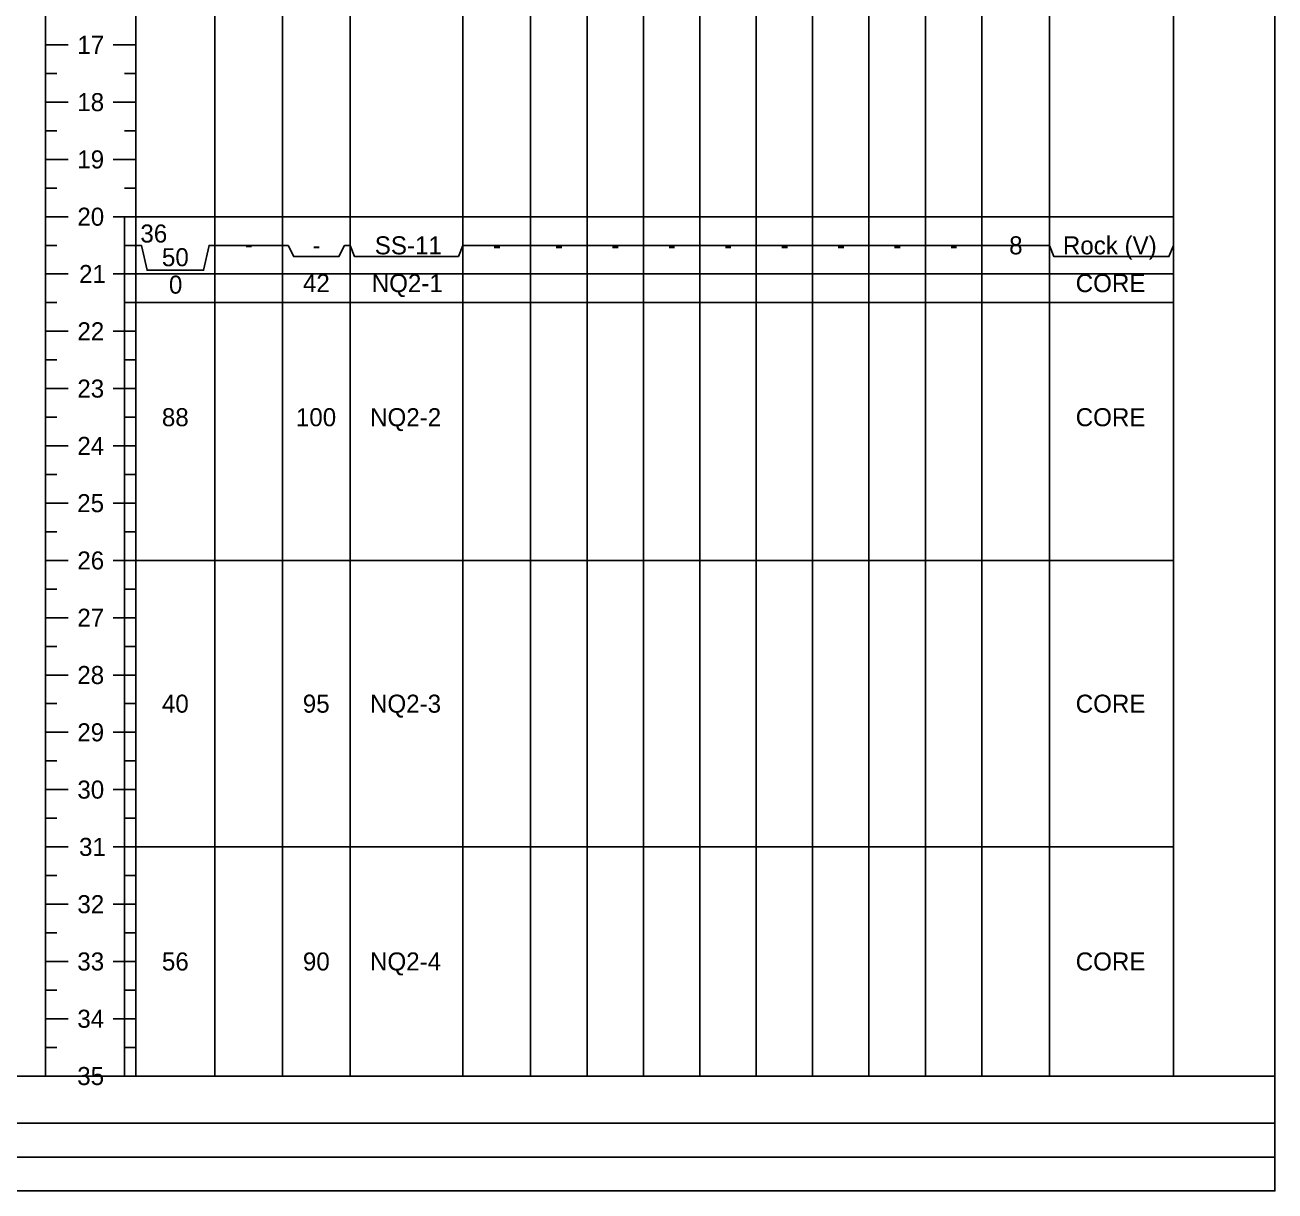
# Model space of a CAD drawing. Extents: x 0 to 0.833, y -0.254 to 0.608.
# Drawn here: x 0.3715 to 0.8333, y -0.2541 to 0.1767 of the extents above; entities that cross this region are included whole.
import ezdxf

# ---------------------------------------------------------------- set-up
doc = ezdxf.new("R2010")
doc.units = 0

msp = doc.modelspace()

# ---------------------------------------------------------------- linework, layer by layer
for points in [[(0, -0.25414), (0.83333, -0.25414), (0.83333, 0.60833), (0, 0.60833)], [(0.40833, 0.08467), (0.4125, 0.08467), (0.4125, 0.10583), (0.40833, 0.10583)], [(0.40833, 0.07408), (0.4125, 0.07408), (0.4125, 0.09525), (0.40833, 0.09525)], [(0.40833, -0.02117), (0.4125, -0.02117), (0.4125, 0.08467), (0.40833, 0.08467)], [(0.40833, -0.127), (0.4125, -0.127), (0.4125, -0.02117), (0.40833, -0.02117)], [(0.40833, -0.21167), (0.4125, -0.21167), (0.4125, -0.127), (0.40833, -0.127)]]:
    msp.add_lwpolyline(points, close=True)
for points in [[(0.4125, 0.55417), (0.4125, -0.21167)], [(0.4125, 0.55417), (0.4125, -0.21167)], [(0.44167, 0.55417), (0.44167, -0.21167)], [(0.46667, 0.55417), (0.46667, -0.21167)], [(0.49167, 0.55417), (0.49167, -0.21167)], [(0.53333, 0.55417), (0.53333, -0.21167)], [(0.55833, 0.55417), (0.55833, -0.21167)], [(0.6625, 0.55417), (0.6625, -0.21167)], [(0.725, 0.55417), (0.725, -0.21167)], [(0.75, 0.55417), (0.75, -0.21167)], [(0.75, 0.55417), (0.75, -0.21167)], [(0.79583, 0.55417), (0.79583, -0.21167)], [(0.57917, 0.54167), (0.57917, -0.21167)], [(0.6, 0.54167), (0.6, -0.21167)], [(0.62083, 0.54167), (0.62083, -0.21167)], [(0.64167, 0.54167), (0.64167, -0.21167)], [(0.68333, 0.54167), (0.68333, -0.21167)], [(0.70417, 0.54167), (0.70417, -0.21167)], [(0.725, 0.54167), (0.725, -0.21167)], [(0.37917, 0.52917), (0.37917, -0.21167)], [(0.37917, 0.16933), (0.3875, 0.16933)], [(0.37917, 0.16933), (0.38333, 0.16933)], [(0.4125, 0.16933), (0.40417, 0.16933)], [(0.4125, 0.16933), (0.40833, 0.16933)], [(0.37917, 0.15875), (0.38333, 0.15875)], [(0.4125, 0.15875), (0.40833, 0.15875)], [(0.37917, 0.14817), (0.3875, 0.14817)], [(0.37917, 0.14817), (0.38333, 0.14817)], [(0.4125, 0.14817), (0.40417, 0.14817)], [(0.4125, 0.14817), (0.40833, 0.14817)], [(0.37917, 0.13758), (0.38333, 0.13758)], [(0.4125, 0.13758), (0.40833, 0.13758)], [(0.37917, 0.127), (0.3875, 0.127)], [(0.37917, 0.127), (0.38333, 0.127)], [(0.4125, 0.127), (0.40417, 0.127)], [(0.4125, 0.127), (0.40833, 0.127)], [(0.37917, 0.11642), (0.38333, 0.11642)], [(0.4125, 0.11642), (0.40833, 0.11642)], [(0.37917, 0.10583), (0.3875, 0.10583)], [(0.37917, 0.10583), (0.38333, 0.10583)], [(0.4125, 0.10583), (0.40417, 0.10583)], [(0.40833, 0.10583), (0.40833, 0.08467)], [(0.40833, 0.10583), (0.4125, 0.10583)], [(0.4125, 0.10583), (0.40833, 0.10583)], [(0.4125, 0.10583), (0.44167, 0.10583)], [(0.44167, 0.10583), (0.46667, 0.10583)], [(0.46667, 0.10583), (0.49167, 0.10583)], [(0.49167, 0.10583), (0.53333, 0.10583)], [(0.53333, 0.10583), (0.55833, 0.10583)], [(0.55833, 0.10583), (0.57917, 0.10583)], [(0.57917, 0.10583), (0.6, 0.10583)], [(0.6, 0.10583), (0.62083, 0.10583)], [(0.62083, 0.10583), (0.64167, 0.10583)], [(0.64167, 0.10583), (0.6625, 0.10583)], [(0.6625, 0.10583), (0.68333, 0.10583)], [(0.68333, 0.10583), (0.70417, 0.10583)], [(0.70417, 0.10583), (0.725, 0.10583)], [(0.725, 0.10583), (0.75, 0.10583)], [(0.75, 0.10583), (0.79583, 0.10583)], [(0.37917, 0.09525), (0.38333, 0.09525)], [(0.40833, 0.09525), (0.40833, 0.07408)], [(0.40833, 0.09525), (0.4125, 0.09525)], [(0.4125, 0.09525), (0.40833, 0.09525)], [(0.4125, 0.09525), (0.41458, 0.09525), (0.41667, 0.08606), (0.4375, 0.08606), (0.43958, 0.09525), (0.44167, 0.09525)], [(0.44167, 0.09525), (0.46667, 0.09525)], [(0.46667, 0.09525), (0.46875, 0.09525), (0.47083, 0.09112), (0.4875, 0.09112), (0.48958, 0.09525), (0.49167, 0.09525)], [(0.49167, 0.09525), (0.49333, 0.09112), (0.53167, 0.09112), (0.53333, 0.09525)], [(0.53333, 0.09525), (0.55833, 0.09525)], [(0.55833, 0.09525), (0.57917, 0.09525)], [(0.57917, 0.09525), (0.6, 0.09525)], [(0.6, 0.09525), (0.62083, 0.09525)], [(0.62083, 0.09525), (0.64167, 0.09525)], [(0.64167, 0.09525), (0.6625, 0.09525)], [(0.6625, 0.09525), (0.68333, 0.09525)], [(0.68333, 0.09525), (0.70417, 0.09525)], [(0.70417, 0.09525), (0.725, 0.09525)], [(0.725, 0.09525), (0.75, 0.09525)], [(0.75, 0.09525), (0.75167, 0.09112), (0.79417, 0.09112), (0.79583, 0.09525)], [(0.37917, 0.08467), (0.3875, 0.08467)], [(0.37917, 0.08467), (0.38333, 0.08467)], [(0.4125, 0.08467), (0.40417, 0.08467)], [(0.40833, 0.08467), (0.4125, 0.08467)], [(0.40833, 0.08467), (0.40833, -0.02117)], [(0.40833, 0.08467), (0.4125, 0.08467)], [(0.4125, 0.08467), (0.40833, 0.08467)], [(0.4125, 0.08467), (0.44167, 0.08467)], [(0.4125, 0.08467), (0.44167, 0.08467)], [(0.44167, 0.08467), (0.46667, 0.08467)], [(0.44167, 0.08467), (0.46667, 0.08467)], [(0.46667, 0.08467), (0.49167, 0.08467)], [(0.46667, 0.08467), (0.49167, 0.08467)], [(0.49167, 0.08467), (0.53333, 0.08467)], [(0.49167, 0.08467), (0.53333, 0.08467)], [(0.53333, 0.08467), (0.55833, 0.08467)], [(0.53333, 0.08467), (0.55833, 0.08467)], [(0.55833, 0.08467), (0.57917, 0.08467)], [(0.55833, 0.08467), (0.57917, 0.08467)], [(0.57917, 0.08467), (0.6, 0.08467)], [(0.57917, 0.08467), (0.6, 0.08467)], [(0.6, 0.08467), (0.62083, 0.08467)], [(0.6, 0.08467), (0.62083, 0.08467)], [(0.62083, 0.08467), (0.64167, 0.08467)], [(0.62083, 0.08467), (0.64167, 0.08467)], [(0.64167, 0.08467), (0.6625, 0.08467)], [(0.64167, 0.08467), (0.6625, 0.08467)], [(0.6625, 0.08467), (0.68333, 0.08467)], [(0.6625, 0.08467), (0.68333, 0.08467)], [(0.68333, 0.08467), (0.70417, 0.08467)], [(0.68333, 0.08467), (0.70417, 0.08467)], [(0.70417, 0.08467), (0.725, 0.08467)], [(0.70417, 0.08467), (0.725, 0.08467)], [(0.725, 0.08467), (0.75, 0.08467)], [(0.725, 0.08467), (0.75, 0.08467)], [(0.75, 0.08467), (0.79583, 0.08467)], [(0.75, 0.08467), (0.79583, 0.08467)], [(0.37917, 0.07408), (0.38333, 0.07408)], [(0.40833, 0.07408), (0.4125, 0.07408)], [(0.4125, 0.07408), (0.40833, 0.07408)], [(0.4125, 0.07408), (0.44167, 0.07408)], [(0.44167, 0.07408), (0.46667, 0.07408)], [(0.46667, 0.07408), (0.49167, 0.07408)], [(0.49167, 0.07408), (0.53333, 0.07408)], [(0.53333, 0.07408), (0.55833, 0.07408)], [(0.55833, 0.07408), (0.57917, 0.07408)], [(0.57917, 0.07408), (0.6, 0.07408)], [(0.6, 0.07408), (0.62083, 0.07408)], [(0.62083, 0.07408), (0.64167, 0.07408)], [(0.64167, 0.07408), (0.6625, 0.07408)], [(0.6625, 0.07408), (0.68333, 0.07408)], [(0.68333, 0.07408), (0.70417, 0.07408)], [(0.70417, 0.07408), (0.725, 0.07408)], [(0.725, 0.07408), (0.75, 0.07408)], [(0.75, 0.07408), (0.79583, 0.07408)], [(0.37917, 0.0635), (0.3875, 0.0635)], [(0.37917, 0.0635), (0.38333, 0.0635)], [(0.4125, 0.0635), (0.40417, 0.0635)], [(0.4125, 0.0635), (0.40833, 0.0635)], [(0.37917, 0.05292), (0.38333, 0.05292)], [(0.4125, 0.05292), (0.40833, 0.05292)], [(0.37917, 0.04233), (0.3875, 0.04233)], [(0.37917, 0.04233), (0.38333, 0.04233)], [(0.4125, 0.04233), (0.40417, 0.04233)], [(0.4125, 0.04233), (0.40833, 0.04233)], [(0.37917, 0.03175), (0.38333, 0.03175)], [(0.4125, 0.03175), (0.40833, 0.03175)], [(0.37917, 0.02117), (0.3875, 0.02117)], [(0.37917, 0.02117), (0.38333, 0.02117)], [(0.4125, 0.02117), (0.40417, 0.02117)], [(0.4125, 0.02117), (0.40833, 0.02117)], [(0.37917, 0.01058), (0.38333, 0.01058)], [(0.4125, 0.01058), (0.40833, 0.01058)], [(0.37917, 0), (0.3875, 0)], [(0.37917, 0), (0.38333, 0)], [(0.4125, 0), (0.40417, 0)], [(0.4125, 0), (0.40833, 0)], [(0.37917, -0.01058), (0.38333, -0.01058)], [(0.4125, -0.01058), (0.40833, -0.01058)], [(0.37917, -0.02117), (0.3875, -0.02117)], [(0.37917, -0.02117), (0.38333, -0.02117)], [(0.4125, -0.02117), (0.40417, -0.02117)], [(0.40833, -0.02117), (0.4125, -0.02117)], [(0.40833, -0.02117), (0.40833, -0.127)], [(0.40833, -0.02117), (0.4125, -0.02117)], [(0.4125, -0.02117), (0.40833, -0.02117)], [(0.4125, -0.02117), (0.44167, -0.02117)], [(0.44167, -0.02117), (0.46667, -0.02117)], [(0.46667, -0.02117), (0.49167, -0.02117)], [(0.49167, -0.02117), (0.53333, -0.02117)], [(0.53333, -0.02117), (0.55833, -0.02117)], [(0.55833, -0.02117), (0.57917, -0.02117)], [(0.57917, -0.02117), (0.6, -0.02117)], [(0.6, -0.02117), (0.62083, -0.02117)], [(0.62083, -0.02117), (0.64167, -0.02117)], [(0.64167, -0.02117), (0.6625, -0.02117)], [(0.6625, -0.02117), (0.68333, -0.02117)], [(0.68333, -0.02117), (0.70417, -0.02117)], [(0.70417, -0.02117), (0.725, -0.02117)], [(0.725, -0.02117), (0.75, -0.02117)], [(0.75, -0.02117), (0.79583, -0.02117)], [(0.37917, -0.03175), (0.38333, -0.03175)], [(0.4125, -0.03175), (0.40833, -0.03175)], [(0.37917, -0.04233), (0.3875, -0.04233)], [(0.37917, -0.04233), (0.38333, -0.04233)], [(0.4125, -0.04233), (0.40417, -0.04233)], [(0.4125, -0.04233), (0.40833, -0.04233)], [(0.37917, -0.05292), (0.38333, -0.05292)], [(0.4125, -0.05292), (0.40833, -0.05292)], [(0.37917, -0.0635), (0.3875, -0.0635)], [(0.37917, -0.0635), (0.38333, -0.0635)], [(0.4125, -0.0635), (0.40417, -0.0635)], [(0.4125, -0.0635), (0.40833, -0.0635)], [(0.37917, -0.07408), (0.38333, -0.07408)], [(0.4125, -0.07408), (0.40833, -0.07408)], [(0.37917, -0.08467), (0.3875, -0.08467)], [(0.37917, -0.08467), (0.38333, -0.08467)], [(0.4125, -0.08467), (0.40417, -0.08467)], [(0.4125, -0.08467), (0.40833, -0.08467)], [(0.37917, -0.09525), (0.38333, -0.09525)], [(0.4125, -0.09525), (0.40833, -0.09525)], [(0.37917, -0.10583), (0.3875, -0.10583)], [(0.37917, -0.10583), (0.38333, -0.10583)], [(0.4125, -0.10583), (0.40417, -0.10583)], [(0.4125, -0.10583), (0.40833, -0.10583)], [(0.37917, -0.11642), (0.38333, -0.11642)], [(0.4125, -0.11642), (0.40833, -0.11642)], [(0.37917, -0.127), (0.3875, -0.127)], [(0.37917, -0.127), (0.38333, -0.127)], [(0.4125, -0.127), (0.40417, -0.127)], [(0.40833, -0.127), (0.4125, -0.127)], [(0.40833, -0.127), (0.40833, -0.21167)], [(0.40833, -0.127), (0.4125, -0.127)], [(0.4125, -0.127), (0.40833, -0.127)], [(0.4125, -0.127), (0.44167, -0.127)], [(0.44167, -0.127), (0.46667, -0.127)], [(0.46667, -0.127), (0.49167, -0.127)], [(0.49167, -0.127), (0.53333, -0.127)], [(0.53333, -0.127), (0.55833, -0.127)], [(0.55833, -0.127), (0.57917, -0.127)], [(0.57917, -0.127), (0.6, -0.127)], [(0.6, -0.127), (0.62083, -0.127)], [(0.62083, -0.127), (0.64167, -0.127)], [(0.64167, -0.127), (0.6625, -0.127)], [(0.6625, -0.127), (0.68333, -0.127)], [(0.68333, -0.127), (0.70417, -0.127)], [(0.70417, -0.127), (0.725, -0.127)], [(0.725, -0.127), (0.75, -0.127)], [(0.75, -0.127), (0.79583, -0.127)], [(0.37917, -0.13758), (0.38333, -0.13758)], [(0.4125, -0.13758), (0.40833, -0.13758)], [(0, -0.14164), (0, -0.25414), (0.83333, -0.25414), (0.83333, -0.14164)], [(0.37917, -0.14817), (0.3875, -0.14817)], [(0.37917, -0.14817), (0.38333, -0.14817)], [(0.4125, -0.14817), (0.40417, -0.14817)], [(0.4125, -0.14817), (0.40833, -0.14817)], [(0.37917, -0.15875), (0.38333, -0.15875)], [(0.4125, -0.15875), (0.40833, -0.15875)], [(0.37917, -0.16933), (0.3875, -0.16933)], [(0.37917, -0.16933), (0.38333, -0.16933)], [(0.4125, -0.16933), (0.40417, -0.16933)], [(0.4125, -0.16933), (0.40833, -0.16933)], [(0.37917, -0.17992), (0.38333, -0.17992)], [(0.4125, -0.17992), (0.40833, -0.17992)], [(0.37917, -0.1905), (0.3875, -0.1905)], [(0.37917, -0.1905), (0.38333, -0.1905)], [(0.4125, -0.1905), (0.40417, -0.1905)], [(0.4125, -0.1905), (0.40833, -0.1905)], [(0.37917, -0.20108), (0.38333, -0.20108)], [(0.4125, -0.20108), (0.40833, -0.20108)], [(0.33333, -0.21167), (0.37917, -0.21167)], [(0.37917, -0.21167), (0.4125, -0.21167)], [(0.37917, -0.21167), (0.3875, -0.21167)], [(0.37917, -0.21167), (0.38333, -0.21167)], [(0.37917, -0.21167), (0.39583, -0.21167)], [(0.4125, -0.21167), (0.39583, -0.21167)], [(0.4125, -0.21167), (0.40417, -0.21167)], [(0.40833, -0.21167), (0.4125, -0.21167)], [(0.40833, -0.21167), (0.4125, -0.21167)], [(0.4125, -0.21167), (0.40833, -0.21167)], [(0.4125, -0.21167), (0.44167, -0.21167)], [(0.44167, -0.21167), (0.46667, -0.21167)], [(0.46667, -0.21167), (0.49167, -0.21167)], [(0.49167, -0.21167), (0.53333, -0.21167)], [(0.53333, -0.21167), (0.55833, -0.21167)], [(0.55833, -0.21167), (0.57917, -0.21167)], [(0.57917, -0.21167), (0.6, -0.21167)], [(0.6, -0.21167), (0.62083, -0.21167)], [(0.62083, -0.21167), (0.64167, -0.21167)], [(0.64167, -0.21167), (0.6625, -0.21167)], [(0.6625, -0.21167), (0.68333, -0.21167)], [(0.68333, -0.21167), (0.70417, -0.21167)], [(0.70417, -0.21167), (0.725, -0.21167)], [(0.725, -0.21167), (0.75, -0.21167)], [(0.75, -0.21167), (0.79583, -0.21167)], [(0.79583, -0.21167), (0.83333, -0.21167)], [(0, -0.22914), (0.83333, -0.22914)], [(0, -0.24164), (0.83333, -0.24164)]]:
    msp.add_lwpolyline(points)

# ---------------------------------------------------------------- texts
for s, height, p in [('17', 0.006667, (0.39087, 0.166)), ('18', 0.006667, (0.39086, 0.14483)), ('19', 0.006667, (0.39086, 0.12367)), ('20', 0.006667, (0.39088, 0.1025)), ('36', 0.006667, (0.41417, 0.09629)), ('SS-11', 0.006667, (0.50076, 0.09192)), ('8', 0.00667, (0.73512, 0.09192)), ('Rock (V)', 0.006667, (0.75497, 0.09192)), ('50', 0.006667, (0.42213, 0.08754)), ('-', 0.00667, (0.45276, 0.09233)), ('-', 0.00667, (0.47776, 0.09192)), ('-', 0.00667, (0.54443, 0.09192)), ('-', 0.00667, (0.56734, 0.09192)), ('-', 0.00667, (0.58818, 0.09192)), ('-', 0.00667, (0.60901, 0.09192)), ('-', 0.00667, (0.62984, 0.09192)), ('-', 0.00667, (0.65068, 0.09192)), ('-', 0.00667, (0.67151, 0.09192)), ('-', 0.00667, (0.69234, 0.09192)), ('-', 0.00667, (0.71318, 0.09192)), ('21', 0.006667, (0.39151, 0.08133)), ('0', 0.00667, (0.42472, 0.0774)), ('42', 0.006667, (0.47423, 0.07796)), ('NQ2-1', 0.006667, (0.49964, 0.07796)), ('CORE', 0.006667, (0.75971, 0.07796)), ('22', 0.006667, (0.3909, 0.06017)), ('23', 0.006667, (0.39087, 0.039)), ('88', 0.006667, (0.42211, 0.02842)), ('100', 0.006667, (0.47162, 0.02842)), ('NQ2-2', 0.006667, (0.49903, 0.02842)), ('CORE', 0.006667, (0.75971, 0.02842)), ('24', 0.006667, (0.39088, 0.01783)), ('25', 0.006667, (0.39084, -0.00333)), ('26', 0.006667, (0.39087, -0.0245)), ('27', 0.006667, (0.39087, -0.04567)), ('28', 0.006667, (0.39086, -0.06683)), ('40', 0.006667, (0.42213, -0.07742)), ('95', 0.006667, (0.47417, -0.07742)), ('NQ2-3', 0.006667, (0.499, -0.07742)), ('CORE', 0.006667, (0.75971, -0.07742)), ('29', 0.006667, (0.39086, -0.088)), ('30', 0.006667, (0.39088, -0.10917)), ('31', 0.006667, (0.39151, -0.13033)), ('32', 0.006667, (0.3909, -0.1515)), ('33', 0.006667, (0.39087, -0.17267)), ('56', 0.006667, (0.42212, -0.17267)), ('90', 0.006667, (0.47421, -0.17267)), ('NQ2-4', 0.006667, (0.49901, -0.17267)), ('CORE', 0.006667, (0.75971, -0.17267)), ('34', 0.006667, (0.39088, -0.19383)), ('35', 0.006667, (0.39084, -0.215))]:
    msp.add_text(s, height=height).set_placement(p)

doc.saveas('drawing.dxf')
